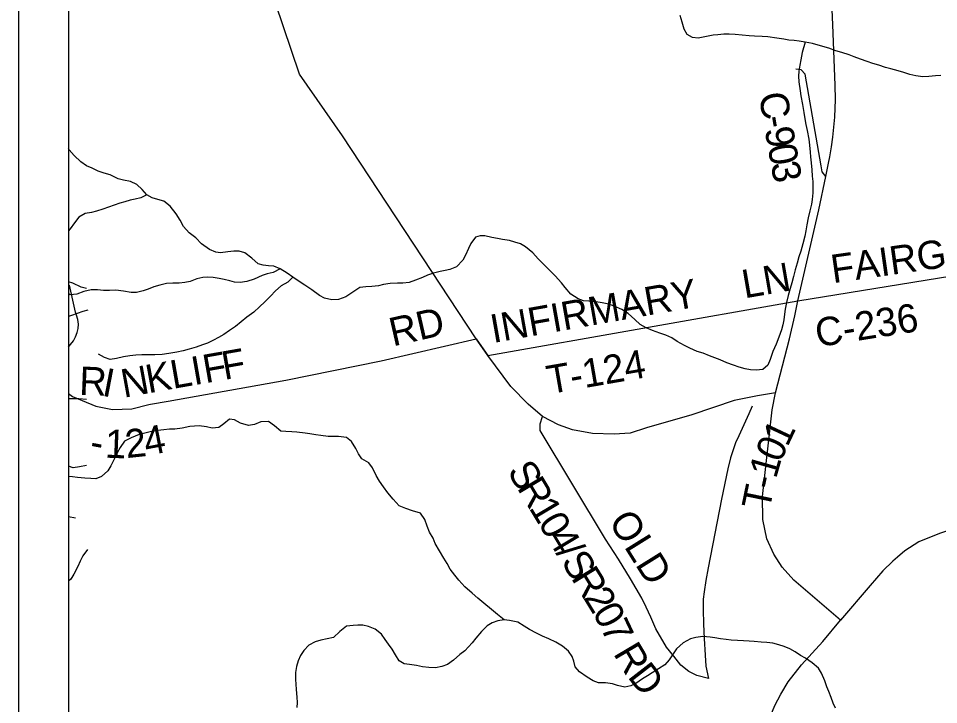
# Model space of a CAD drawing. Extents: x 0 to 34, y 0 to 22.
# Drawn here: x 2 to 3.839, y 18.679 to 20.051 of the extents above; entities that cross this region are included whole.
import ezdxf

# ---------------------------------------------------------------- set-up
doc = ezdxf.new("R2010")
doc.units = 0
for name, color, linetype in [('GM_X_Corporation', 7, 'Continuous'), ('GM_X_County_Road', 7, 'Continuous'), ('GM_X_County_Road_Text', 7, 'Continuous'), ('GM_X_Minor_River', 7, 'Continuous'), ('GM_X_State_Route', 7, 'Continuous'), ('GM_X_Township_Road', 7, 'Continuous'), ('GM_X_Township_Road_Text', 7, 'Continuous'), ('SH_Data', 7, 'Continuous')]:
    doc.layers.add(name, color=color, linetype=linetype)

msp = doc.modelspace()

# ---------------------------------------------------------------- linework, layer by layer
at = {"layer": 'GM_X_Corporation'}
msp.add_line((2.1, 20.9), (2.1, 15.8164), dxfattribs=at)
msp.add_lwpolyline([(4.892, 20.9), (2.1, 20.9), (2.1, 15.9991)], dxfattribs=at)
at = {"layer": 'GM_X_County_Road'}
for points in [[(3.6135, 19.7349), (3.6067, 19.7444), (3.6046, 19.7559), (3.5725, 19.9392), (3.5645, 19.9482), (3.554, 19.9497)], [(3.5575, 19.4864), (3.89, 19.5399), (3.9012, 19.5415), (3.9335, 19.5461), (3.9596, 19.5492), (4.0263, 19.5573), (4.1914, 19.5772)]]:
    msp.add_lwpolyline(points, dxfattribs=at)
at = {"layer": 'GM_X_Minor_River'}
for p, q in [((2.109, 19.5213), (2.1, 19.5241)), ((2.1252, 19.5136), (2.109, 19.5213)), ((2.1358, 19.5108), (2.1252, 19.5136)), ((2.1176, 19.4609), (2.1058, 19.4569)), ((2.1286, 19.4646), (2.1176, 19.4609)), ((2.1385, 19.4676), (2.1286, 19.4646)), ((2.1058, 19.4569), (2.1, 19.455)), ((2.1082, 19.29), (2.1, 19.2903)), ((2.1207, 19.2906), (2.1082, 19.29)), ((2.1358, 19.289), (2.1207, 19.2906)), ((2.1096, 19.1523), (2.1, 19.1558)), ((2.1222, 19.1541), (2.1096, 19.1523)), ((2.1362, 19.1573), (2.1222, 19.1541)), ((2.1378, 18.9889), (2.129, 18.9761)), ((2.1236, 18.9659), (2.119, 18.9553)), ((2.129, 18.9761), (2.1236, 18.9659)), ((2.119, 18.9553), (2.1105, 18.9399)), ((2.1047, 18.9297), (2.1, 18.9255)), ((2.1105, 18.9399), (2.1047, 18.9297))]:
    msp.add_line(p, q, dxfattribs=at)
for points in [[(3.8433, 19.937), (3.8327, 19.9364), (3.8194, 19.935), (3.8073, 19.9343), (3.7937, 19.936), (3.7815, 19.9387), (3.7695, 19.9426), (3.7585, 19.9462), (3.7437, 19.9501), (3.7328, 19.9528), (3.7199, 19.9571), (3.7075, 19.961), (3.6961, 19.9646), (3.6829, 19.9696), (3.6704, 19.9743), (3.6602, 19.9778), (3.6459, 19.9825), (3.6338, 19.9864), (3.6198, 19.9911), (3.6028, 19.9961), (3.5869, 20.0005), (3.5725, 20.0033), (3.5604, 20.0053), (3.5502, 20.0065), (3.54, 20.0077), (3.5297, 20.0097), (3.5161, 20.0117), (3.4976, 20.0142), (3.4862, 20.015), (3.4714, 20.0156), (3.4608, 20.016), (3.4464, 20.0173), (3.4324, 20.0186), (3.4203, 20.0194), (3.4101, 20.0192), (3.3979, 20.0181), (3.3884, 20.0171), (3.3717, 20.0142), (3.3584, 20.0113), (3.3471, 20.0125), (3.3369, 20.0187), (3.3309, 20.0294), (3.3265, 20.0431), (3.3224, 20.0568)], [(3.5725, 20.0033), (3.5667, 19.9828), (3.5639, 19.9684), (3.5615, 19.9575), (3.5599, 19.9457), (3.5594, 19.9355), (3.5601, 19.9241), (3.5622, 19.9062), (3.564, 19.8964), (3.5673, 19.8789), (3.5698, 19.8629), (3.572, 19.85), (3.5738, 19.839), (3.5763, 19.8268), (3.5796, 19.8094), (3.581, 19.7972), (3.5824, 19.7835), (3.5834, 19.7741), (3.5845, 19.7619), (3.5855, 19.7482), (3.5865, 19.7353), (3.5876, 19.7251), (3.5879, 19.7156), (3.5878, 19.7023), (3.5865, 19.6891), (3.5853, 19.6796), (3.5818, 19.666), (3.5786, 19.6523), (3.5755, 19.6383), (3.5735, 19.6262), (3.5719, 19.6156), (3.5679, 19.6005), (3.564, 19.5857), (3.5598, 19.574), (3.5562, 19.5615), (3.5527, 19.5483), (3.5492, 19.5346), (3.5457, 19.5222), (3.5425, 19.5108), (3.5386, 19.4968), (3.5351, 19.4832), (3.5327, 19.4696), (3.5311, 19.4593), (3.5295, 19.4483), (3.5275, 19.4381), (3.5252, 19.4283), (3.5201, 19.4135), (3.5147, 19.3996), (3.5081, 19.3848), (3.5023, 19.3686), (3.4976, 19.3576), (3.4881, 19.3486), (3.4744, 19.3476), (3.4635, 19.3484), (3.4525, 19.3504), (3.4408, 19.3536), (3.429, 19.3575), (3.4158, 19.3625), (3.4026, 19.3683), (3.392, 19.3722), (3.3815, 19.3765), (3.3686, 19.3816), (3.3569, 19.3851), (3.3418, 19.3917), (3.3312, 19.3967), (3.3165, 19.4052), (3.306, 19.4121), (3.2943, 19.4175), (3.2818, 19.4218), (3.2674, 19.4269), (3.255, 19.4319), (3.2429, 19.4392), (3.232, 19.4492), (3.2188, 19.4607), (3.206, 19.4692), (3.1909, 19.4757), (3.1799, 19.4793), (3.1667, 19.482), (3.1538, 19.484), (3.1398, 19.4853), (3.1292, 19.4865), (3.119, 19.4904), (3.1043, 19.4997), (3.0931, 19.5127), (3.0852, 19.5222), (3.0728, 19.536), (3.0619, 19.5471), (3.0499, 19.559), (3.0386, 19.5701), (3.0281, 19.5823), (3.0138, 19.5942), (3.0036, 19.6004), (2.9923, 19.6035), (2.9817, 19.6066), (2.9673, 19.609), (2.9574, 19.6106), (2.9461, 19.613), (2.9325, 19.6162), (2.923, 19.6163), (2.9135, 19.6133), (2.9043, 19.6009)], [(2.9043, 19.6009), (2.8993, 19.5907), (2.8935, 19.5775), (2.8881, 19.5677), (2.8759, 19.5545), (2.8625, 19.5489), (2.8531, 19.5467), (2.8428, 19.5449), (2.8295, 19.5416), (2.8174, 19.5376), (2.8078, 19.5331), (2.7934, 19.5276), (2.7808, 19.5231), (2.7683, 19.5217), (2.7577, 19.5218), (2.7433, 19.5212), (2.73, 19.5187), (2.7198, 19.5161), (2.7065, 19.5151), (2.6944, 19.5141), (2.6826, 19.5127), (2.6704, 19.5048), (2.6544, 19.4943), (2.6396, 19.4891), (2.6267, 19.4881), (2.6119, 19.4913), (2.6021, 19.4971), (2.5863, 19.5082), (2.5723, 19.5175), (2.5592, 19.5263), (2.5482, 19.5336), (2.5373, 19.5417), (2.523, 19.5505), (2.5105, 19.5552), (2.4999, 19.556), (2.4893, 19.5573), (2.4795, 19.5604), (2.4663, 19.5712), (2.4527, 19.5823), (2.4414, 19.5854), (2.4304, 19.5855), (2.4183, 19.5841), (2.4042, 19.582), (2.3944, 19.5836), (2.3819, 19.589), (2.3657, 19.6005), (2.3545, 19.612), (2.3413, 19.622), (2.33, 19.635), (2.3233, 19.6472), (2.3155, 19.6605), (2.3031, 19.6758), (2.2907, 19.6858), (2.2789, 19.6886), (2.2672, 19.6921), (2.2566, 19.6979), (2.2473, 19.7089), (2.2364, 19.7189), (2.2239, 19.7247), (2.2099, 19.7275), (2.1993, 19.7302), (2.1831, 19.738), (2.1717, 19.7415), (2.1593, 19.7458), (2.1472, 19.7512), (2.1359, 19.7559), (2.1246, 19.7639), (2.1114, 19.7766), (2.1016, 19.788), (2.1, 19.7905)], [(2.2566, 19.6979), (2.2445, 19.6923), (2.2331, 19.6897), (2.2232, 19.6875), (2.2126, 19.6842), (2.2027, 19.6813), (2.1917, 19.6776), (2.1799, 19.6735), (2.1685, 19.6698), (2.1563, 19.6654), (2.1461, 19.6628), (2.1335, 19.6607), (2.121, 19.6532), (2.1121, 19.6419), (2.1033, 19.6299), (2.1, 19.626)], [(2.523, 19.5505), (2.5089, 19.5427), (2.4971, 19.5405), (2.4872, 19.5368), (2.4709, 19.5298), (2.4564, 19.525), (2.4435, 19.5228), (2.4322, 19.5237), (2.4223, 19.5264), (2.4114, 19.5292), (2.4015, 19.5312), (2.3894, 19.5328), (2.3788, 19.5336), (2.3686, 19.533), (2.3568, 19.5301), (2.3435, 19.5252), (2.3329, 19.5227), (2.3215, 19.5217), (2.3086, 19.5218), (2.2961, 19.5207), (2.2824, 19.5178), (2.271, 19.5141), (2.2592, 19.5097), (2.2493, 19.5064), (2.2357, 19.5031), (2.2254, 19.5032), (2.2099, 19.5056), (2.1948, 19.5073), (2.1822, 19.5066), (2.1701, 19.5071), (2.158, 19.508), (2.1451, 19.5081), (2.1311, 19.5048), (2.1166, 19.4993), (2.1037, 19.4982), (2.1, 19.5005)], [(2.5482, 19.5336), (2.5383, 19.5235), (2.5253, 19.516), (2.5139, 19.5062), (2.5036, 19.4953), (2.4928, 19.4844), (2.4818, 19.4739), (2.4707, 19.4638), (2.4566, 19.4533), (2.4455, 19.4439), (2.4337, 19.4349), (2.4219, 19.4267), (2.4104, 19.4192), (2.3998, 19.4132), (2.3899, 19.4076), (2.3781, 19.4017), (2.3682, 19.398), (2.3553, 19.3935), (2.3416, 19.3895), (2.3294, 19.3862), (2.3165, 19.3836), (2.3009, 19.3807), (2.2873, 19.379), (2.2729, 19.378), (2.2604, 19.3785), (2.2467, 19.3782), (2.2346, 19.3776), (2.2228, 19.3761), (2.2103, 19.374), (2.1963, 19.3707), (2.1837, 19.3689), (2.172, 19.3732), (2.1599, 19.3794)], [(3.449, 18.8062), (3.4369, 18.807), (3.4244, 18.8079), (3.4145, 18.8091), (3.4035, 18.8104), (3.3922, 18.8124), (3.3823, 18.8136), (3.3679, 18.8149), (3.3539, 18.8131), (3.3433, 18.8102), (3.3284, 18.8023), (3.3151, 18.7907), (3.3074, 18.7783), (3.3005, 18.7681), (3.292, 18.7583), (3.2791, 18.7505), (3.2669, 18.7426), (3.2574, 18.7366), (3.2471, 18.7303), (3.2341, 18.7213), (3.2238, 18.7164), (3.2121, 18.7139), (3.1977, 18.7171), (3.1871, 18.7206), (3.1731, 18.7222), (3.1595, 18.7227), (3.1489, 18.7262), (3.1368, 18.7336), (3.1214, 18.7447), (3.1131, 18.7543), (3.1098, 18.7657), (3.1069, 18.7752), (3.0997, 18.7859), (3.0873, 18.7958), (3.0741, 18.8035), (3.0602, 18.8105), (3.0477, 18.8155), (3.0352, 18.8217), (3.0213, 18.8291), (3.0107, 18.836), (2.9979, 18.8437), (2.9813, 18.8469), (2.971, 18.8481), (2.9575, 18.8589), (2.9458, 18.8688), (2.9304, 18.8815), (2.9183, 18.8918), (2.9071, 18.9014), (2.8924, 18.9145), (2.88, 18.9275), (2.8725, 18.9378), (2.8631, 18.9496), (2.8572, 18.9607), (2.8504, 18.9717), (2.8418, 18.9866), (2.8332, 19.0007), (2.8288, 19.0118), (2.8217, 19.024), (2.8172, 19.0354), (2.8124, 19.0491), (2.8034, 19.0617), (2.7876, 19.066), (2.774, 19.0707), (2.7611, 19.0765), (2.7487, 19.0899), (2.7382, 19.1025), (2.7296, 19.1143), (2.7214, 19.1258), (2.715, 19.1368), (2.7076, 19.1521), (2.7004, 19.162), (2.6861, 19.1705), (2.6794, 19.18), (2.6745, 19.1911), (2.6659, 19.2052), (2.6558, 19.2132), (2.6399, 19.2149), (2.619, 19.2151), (2.6047, 19.2171), (2.5944, 19.2184), (2.5827, 19.22), (2.5729, 19.2216), (2.5566, 19.2233), (2.5467, 19.2241), (2.5346, 19.225), (2.5248, 19.2258), (2.512, 19.2362), (2.4999, 19.245), (2.4847, 19.244), (2.4718, 19.2388), (2.4597, 19.2367), (2.4438, 19.2417), (2.4317, 19.2483), (2.4219, 19.2499), (2.4108, 19.2402), (2.4009, 19.2327), (2.3872, 19.2313), (2.3759, 19.234), (2.3615, 19.2361), (2.3429, 19.2351), (2.327, 19.2314)], [(2.327, 19.2314), (2.3129, 19.2297), (2.3019, 19.2294), (2.2909, 19.2284), (2.2788, 19.2269), (2.2663, 19.2248), (2.2526, 19.2219), (2.2416, 19.2189), (2.2252, 19.2123), (2.2119, 19.2056), (2.2031, 19.1927), (2.1977, 19.1826), (2.193, 19.172), (2.1846, 19.1565), (2.1788, 19.1463), (2.1662, 19.1351), (2.1548, 19.1306), (2.1449, 19.1307), (2.1328, 19.1316), (2.1184, 19.1332), (2.1078, 19.1344), (2.1, 19.1347)], [(2.971, 18.8481), (2.9581, 18.8463), (2.9471, 18.8426), (2.9368, 18.8367), (2.9254, 18.825), (2.9143, 18.8118), (2.907, 18.8021), (2.8924, 18.7866), (2.8825, 18.7788), (2.8695, 18.7679), (2.8573, 18.7589), (2.8463, 18.7552), (2.8334, 18.7527), (2.8201, 18.7528), (2.8076, 18.7544), (2.7955, 18.7568), (2.7819, 18.7588), (2.7713, 18.7604), (2.7607, 18.7666), (2.754, 18.7784), (2.7473, 18.7895), (2.7394, 18.7994), (2.7331, 18.8093), (2.7256, 18.8197), (2.7128, 18.83), (2.6996, 18.8351), (2.6886, 18.8378), (2.6787, 18.8375), (2.6689, 18.8369), (2.6556, 18.8355), (2.6426, 18.8253), (2.63, 18.8133), (2.6171, 18.8104), (2.6042, 18.8079), (2.5928, 18.8042), (2.5802, 18.7978), (2.5703, 18.7873), (2.5641, 18.7768), (2.5591, 18.7666), (2.556, 18.7552), (2.554, 18.7431), (2.5539, 18.7294), (2.5542, 18.7196), (2.5552, 18.7089), (2.5566, 18.6938), (2.5569, 18.6831), (2.5564, 18.6733)], [(3.6328, 18.6717), (3.6283, 18.682), (3.6246, 18.693), (3.6198, 18.7052), (3.6157, 18.7147), (3.6117, 18.7265), (3.6053, 18.7418), (3.599, 18.7517), (3.5862, 18.7624), (3.573, 18.7717), (3.5628, 18.7771), (3.5523, 18.7844), (3.5417, 18.7901), (3.5307, 18.7948), (3.5198, 18.7987), (3.5077, 18.8015), (3.4959, 18.8031), (3.4846, 18.8039), (3.4702, 18.8052), (3.4607, 18.8057), (3.449, 18.8062)]]:
    msp.add_lwpolyline(points, dxfattribs=at)
at = {"layer": 'GM_X_State_Route'}
msp.add_line((2.9382, 19.3772), (2.9152, 19.41), dxfattribs=at)
for points in [[(2.9152, 19.41), (2.6475, 19.8161), (2.5621, 19.9394), (2.4022, 20.4134), (2.3745, 20.454), (2.3388, 20.4877), (2.2702, 20.5289), (2.1759, 20.6081), (2.1, 20.6834)], [(3.6216, 19.7741), (3.6251, 19.7939), (3.628, 19.8136), (3.632, 19.8534), (3.6329, 19.8885), (3.6326, 19.9177), (3.6277, 20.0383), (3.625, 20.0992), (3.625, 20.1253), (3.6253, 20.1473), (3.6263, 20.1648), (3.6286, 20.189), (3.6318, 20.2167), (3.6349, 20.2376), (3.6382, 20.2546), (3.6609, 20.3565), (3.675, 20.418), (3.6819, 20.4482)], [(3.5575, 19.4864), (3.5995, 19.6684), (3.6135, 19.7349), (3.6193, 19.7612), (3.6216, 19.7741)], [(4.8244, 19.6683), (4.5392, 19.3496), (4.5182, 19.3268), (4.4976, 19.3059), (4.4745, 19.2848), (4.4544, 19.2684), (4.4263, 19.2464), (4.3952, 19.2247), (4.3638, 19.2049), (4.3247, 19.1837), (4.2913, 19.1678), (4.2568, 19.1533), (4.2195, 19.1403), (4.1126, 19.1069), (3.9165, 19.0455), (3.8411, 19.0212), (3.7999, 19.0044), (3.7716, 18.9862), (3.7568, 18.9738)], [(3.5132, 19.3022), (3.5412, 19.4102), (3.5517, 19.4561), (3.5575, 19.4864)], [(3.5132, 19.3022), (3.4774, 19.2964), (3.4307, 19.2867), (3.3462, 19.2585), (3.2555, 19.2321), (3.2229, 19.2216), (3.1904, 19.2198), (3.1472, 19.2207), (3.1076, 19.2286), (3.0795, 19.2383), (3.0478, 19.255), (3.0187, 19.2797), (2.9844, 19.3149), (2.9382, 19.3772)], [(3.6434, 18.8475), (3.5499, 18.9276), (3.5265, 18.9539), (3.5096, 18.9794), (3.4959, 19.0104), (3.4877, 19.0489), (3.4875, 19.0952), (3.5067, 19.2685), (3.5132, 19.3022)], [(3.7568, 18.9738), (3.7474, 18.966), (3.7278, 18.9464), (3.7022, 18.9168), (3.6434, 18.8475)], [(3.5007, 18.476), (3.4926, 18.5178), (3.4879, 18.5603), (3.4886, 18.5886), (3.494, 18.627), (3.5027, 18.6546), (3.5115, 18.6769), (3.5236, 18.6998), (3.5385, 18.7247), (3.5654, 18.7584), (3.6079, 18.8049), (3.6434, 18.8475)]]:
    msp.add_lwpolyline(points, dxfattribs=at)
at = {"layer": 'GM_X_Township_Road'}
for p, q in [((2.9382, 19.3772), (3.5575, 19.4864)), ((2.9152, 19.41), (2.9382, 19.3772)), ((2.1, 19.0552), (2.114, 19.0525))]:
    msp.add_line(p, q, dxfattribs=at)
for points in [[(2.1, 19.3937), (2.1041, 19.3992), (2.1101, 19.4065), (2.1143, 19.4141), (2.1177, 19.423), (2.1194, 19.431), (2.1199, 19.4394), (2.119, 19.4489), (2.1163, 19.4573), (2.1139, 19.4637), (2.1024, 19.5177)], [(2.2604, 19.2788), (2.2642, 19.2797), (2.2993, 19.2854), (2.5348, 19.3278), (2.7249, 19.3663), (2.9152, 19.41)], [(2.1, 19.301), (2.1083, 19.2952), (2.155, 19.2756), (2.1881, 19.2691), (2.2269, 19.2705), (2.2604, 19.2788)], [(3.4668, 19.2759), (3.4599, 19.2605), (3.4397, 19.2166), (3.433, 19.2022), (3.4291, 19.1906), (3.4232, 19.1725), (3.4178, 19.1501), (3.4055, 19.0894), (3.3783, 18.9525), (3.3736, 18.927), (3.3705, 18.9045), (3.3689, 18.89), (3.3689, 18.8691), (3.3695, 18.84), (3.3709, 18.8113), (3.3724, 18.7779), (3.374, 18.7555), (3.3795, 18.7311)], [(3.3795, 18.7311), (3.3557, 18.7369), (3.3398, 18.7451), (3.324, 18.7577), (3.3097, 18.7758), (3.2955, 18.7938), (3.2742, 18.8305), (3.2638, 18.854), (3.2545, 18.8737), (3.2457, 18.8918), (3.2233, 18.9301), (3.1992, 18.9695), (3.1735, 19.0094), (3.0425, 19.2272), (3.0425, 19.2401), (3.0478, 19.255)]]:
    msp.add_lwpolyline(points, dxfattribs=at)
at = {"layer": 'SH_Data'}
for p, q in [((2, 21), (2, 14)), ((2.1, 20.9), (2.1, 14.1))]:
    msp.add_line(p, q, dxfattribs=at)

# ---------------------------------------------------------------- texts
at = {"layer": 'GM_X_County_Road_Text'}
for s, height, rotation, p in [('C', 0.0568, 279.7536, (3.4795, 19.8991)), ('-', 0.0568, 279.7581, (3.4874, 19.8531)), ('9', 0.0568, 279.7718, (3.4913, 19.8301)), ('0', 0.0568, 279.8728, (3.4973, 19.7955)), ('3', 0.0568, 280.374, (3.5034, 19.7605)), ('FAIRGROUNDS', 0.056818, 8.1161, (3.628, 19.5213)), ('C-236', 0.05682, 9.1003, (3.5974, 19.3934))]:
    msp.add_text(s, height=height, rotation=rotation, dxfattribs=at).set_placement(p)
at = {"layer": 'GM_X_Township_Road_Text'}
for s, height, rotation, p in [('LN', 0.05682, 9.8003, (3.4513, 19.491)), ('INFIRMARY', 0.05682, 10.086, (2.9487, 19.4018)), ('RD', 0.05682, 12.8483, (2.7485, 19.3949)), ('F', 0.0568, 9.9279, (2.3737, 19.3214)), ('F', 0.0568, 9.9292, (2.4115, 19.328)), ('T-124', 0.05682, 9.8778, (3.0612, 19.2995)), ('L', 0.0568, 9.9365, (2.3089, 19.3101)), ('I', 0.0568, 9.932, (2.3508, 19.3174)), ('R', 0.0568, 357.7553, (2.1208, 19.2983)), ('I', 0.0568, 349.1157, (2.1652, 19.2968)), ('N', 0.0568, 10.3274, (2.2106, 19.2923)), ('K', 0.0568, 10.2247, (2.2598, 19.3012)), ('4', 0.0568, 11.0153, (2.2562, 19.1761)), ('1', 0.0568, 64.885, (3.5369, 19.1924)), ('1', 0.0568, 357.807, (2.1722, 19.1727)), ('2', 0.0568, 6.0771, (2.2161, 19.1716)), ('-', 0.0568, 349.0857, (2.14, 19.1782)), ('0', 0.0568, 66.2636, (3.5229, 19.1607)), ('S', 0.0568, 300.7763, (2.9759, 19.1456)), ('1', 0.0568, 74.204, (3.5141, 19.1289)), ('R', 0.0568, 300.7737, (2.9955, 19.1126)), ('-', 0.0568, 77.969, (3.5095, 19.1071)), ('T', 0.0568, 78.3749, (3.5009, 19.0655)), ('1', 0.0568, 300.7907, (3.0194, 19.0725)), ('0', 0.0568, 300.8236, (3.0374, 19.0424)), ('OLD', 0.05682, 301.971, (3.1782, 19.0452)), ('4', 0.0568, 300.9264, (3.0554, 19.0123)), ('/', 0.0568, 301.0547, (3.0734, 18.9821)), ('S', 0.0568, 301.2265, (3.0834, 18.9655)), ('R', 0.0568, 301.675, (3.1035, 18.9323)), ('2', 0.0568, 301.4466, (3.128, 18.8927)), ('0', 0.0568, 299.1143, (3.146, 18.8633)), ('7', 0.0568, 295.3454, (3.1625, 18.8336)), ('R', 0.0568, 300.6558, (3.188, 18.7812)), ('D', 0.0568, 307.7389, (3.2162, 18.7346))]:
    msp.add_text(s, height=height, rotation=rotation, dxfattribs=at).set_placement(p)

doc.saveas('drawing.dxf')
